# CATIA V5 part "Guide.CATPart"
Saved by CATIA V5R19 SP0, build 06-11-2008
Part number: Guide
Publications: "L", "H", "P", "r"
Bounding box of the stored display mesh (mm): x 0 to 40, y 0 to 40, z 0 to 10
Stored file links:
  G:\EU_thinkMotion\CFAO_2010\MMS_groupe3\MMS_groupe3\A reprendre\evulliez\evulliez\Guide.CATPart
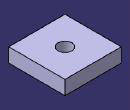
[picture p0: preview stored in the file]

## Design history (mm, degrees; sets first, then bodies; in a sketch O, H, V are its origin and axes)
Parameters
  L = 40 mm
  H = 40 mm
  P = 10 mm
  r = 5 mm
Body1 (main body)
  Sketch1 on yz-plane, origin (0, 0, 0), H (0, 1, 0), V (0, 0, 1)
    line L1 (0, 0) -> (40, 0)
    line L2 (40, 0) -> (40, 10)
    line L3 (40, 10) -> (0, 10)
    line L4 (0, 10) -> (0, 0)
    length L2 = 10 {= P}
    length L3 = 40 {= L}
    horizontal: L1 H, L3 H
    vertical: L2 V, L4 V
  Pad1: profile Sketch1, direction (1, 0, 0), length 40 {= H}
  Point1: type OnPlane, Support face of Pad1 from Sketch1.L3, H 20 {= H -20mm}, V 20 {= L /2}, Direction (1, 0, 0)
  Sketch2 on face of Pad1 from Sketch1.L3, origin (30, 20, 10), H (1, 0, 0), V (0, 1, 0)
    point P1 (-10, 0)
    reference projected point E1 (-10, 0) from Point1
    coincidence: E1 P1
  Hole1: placed by Sketch2, at (20, 20, 10) direction (0, 0, -1), diameter 10 {= 2*r}, through (limit type 3)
